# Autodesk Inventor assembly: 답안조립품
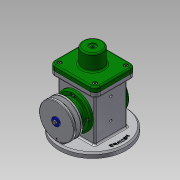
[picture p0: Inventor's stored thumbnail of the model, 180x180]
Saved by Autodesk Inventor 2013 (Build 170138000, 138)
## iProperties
Created: 2019-08
Part Number: 답안조립품
Document SubType Name: Assembly
Designer: default
Author: default
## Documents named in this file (18)
- C:\Users\default.default-PC\Desktop\490804V1015\답안조립품.iam
- C:\Users\default.default-PC\Desktop\490804V1015\본체.ipt
- C:\Users\default.default-PC\Desktop\490804V1015\베어링 17 x 40 x 12.ipt
- C:\Users\default.default-PC\Desktop\490804V1015\편심축.ipt
- C:\Users\default.default-PC\Desktop\490804V1015\뒤커버.ipt
- C:\Users\default.default-PC\Desktop\490804V1015\앞커버.ipt
- C:\Users\default.default-PC\Desktop\490804V1015\키 4 x 4 x 12.ipt
- C:\Users\default.default-PC\Desktop\490804V1015\오일 실 17 30 8.ipt
- C:\Users\default.default-PC\Desktop\490804V1015\볼트 M4 x 8.ipt
- C:\Users\default.default-PC\Desktop\490804V1015\V-벨트풀리.ipt
- C:\Users\default.default-PC\Desktop\490804V1015\와셔 4x16.ipt
- C:\Users\default.default-PC\Desktop\490804V1015\볼트 M4 x 10.ipt
- C:\Users\default.default-PC\Desktop\490804V1015\링크.ipt
- C:\Users\default.default-PC\Desktop\490804V1015\슬라이더.ipt
- C:\Users\default.default-PC\Desktop\490804V1015\클레비스 핀 6 x 22.ipt
- 클레비스 핀 6 x 22.ipt
- C:\Users\default.default-PC\Desktop\490804V1015\E-링.ipt
- C:\Users\default.default-PC\Desktop\490804V1015\덮개.ipt
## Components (2 placed, 2 different names)
1. V-벨트풀리:1
2. E-링:1
